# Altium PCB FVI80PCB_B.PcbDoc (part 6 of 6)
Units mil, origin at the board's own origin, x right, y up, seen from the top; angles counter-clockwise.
Board outline 3540 x 3115 mil, 12 copper layers (Top Layer, Int1(GND), Int2(Signal), Int3(GND), Int4(Signal), Int5 (GND&PW), Int6 (GND&PW), Int7(Signal), Int8(GND), Int9(Signal), Int10(GND), Bottom Layer), stack 77.136 mil thick; 488 components, 321 nets, 1809 pads, 882 vias.
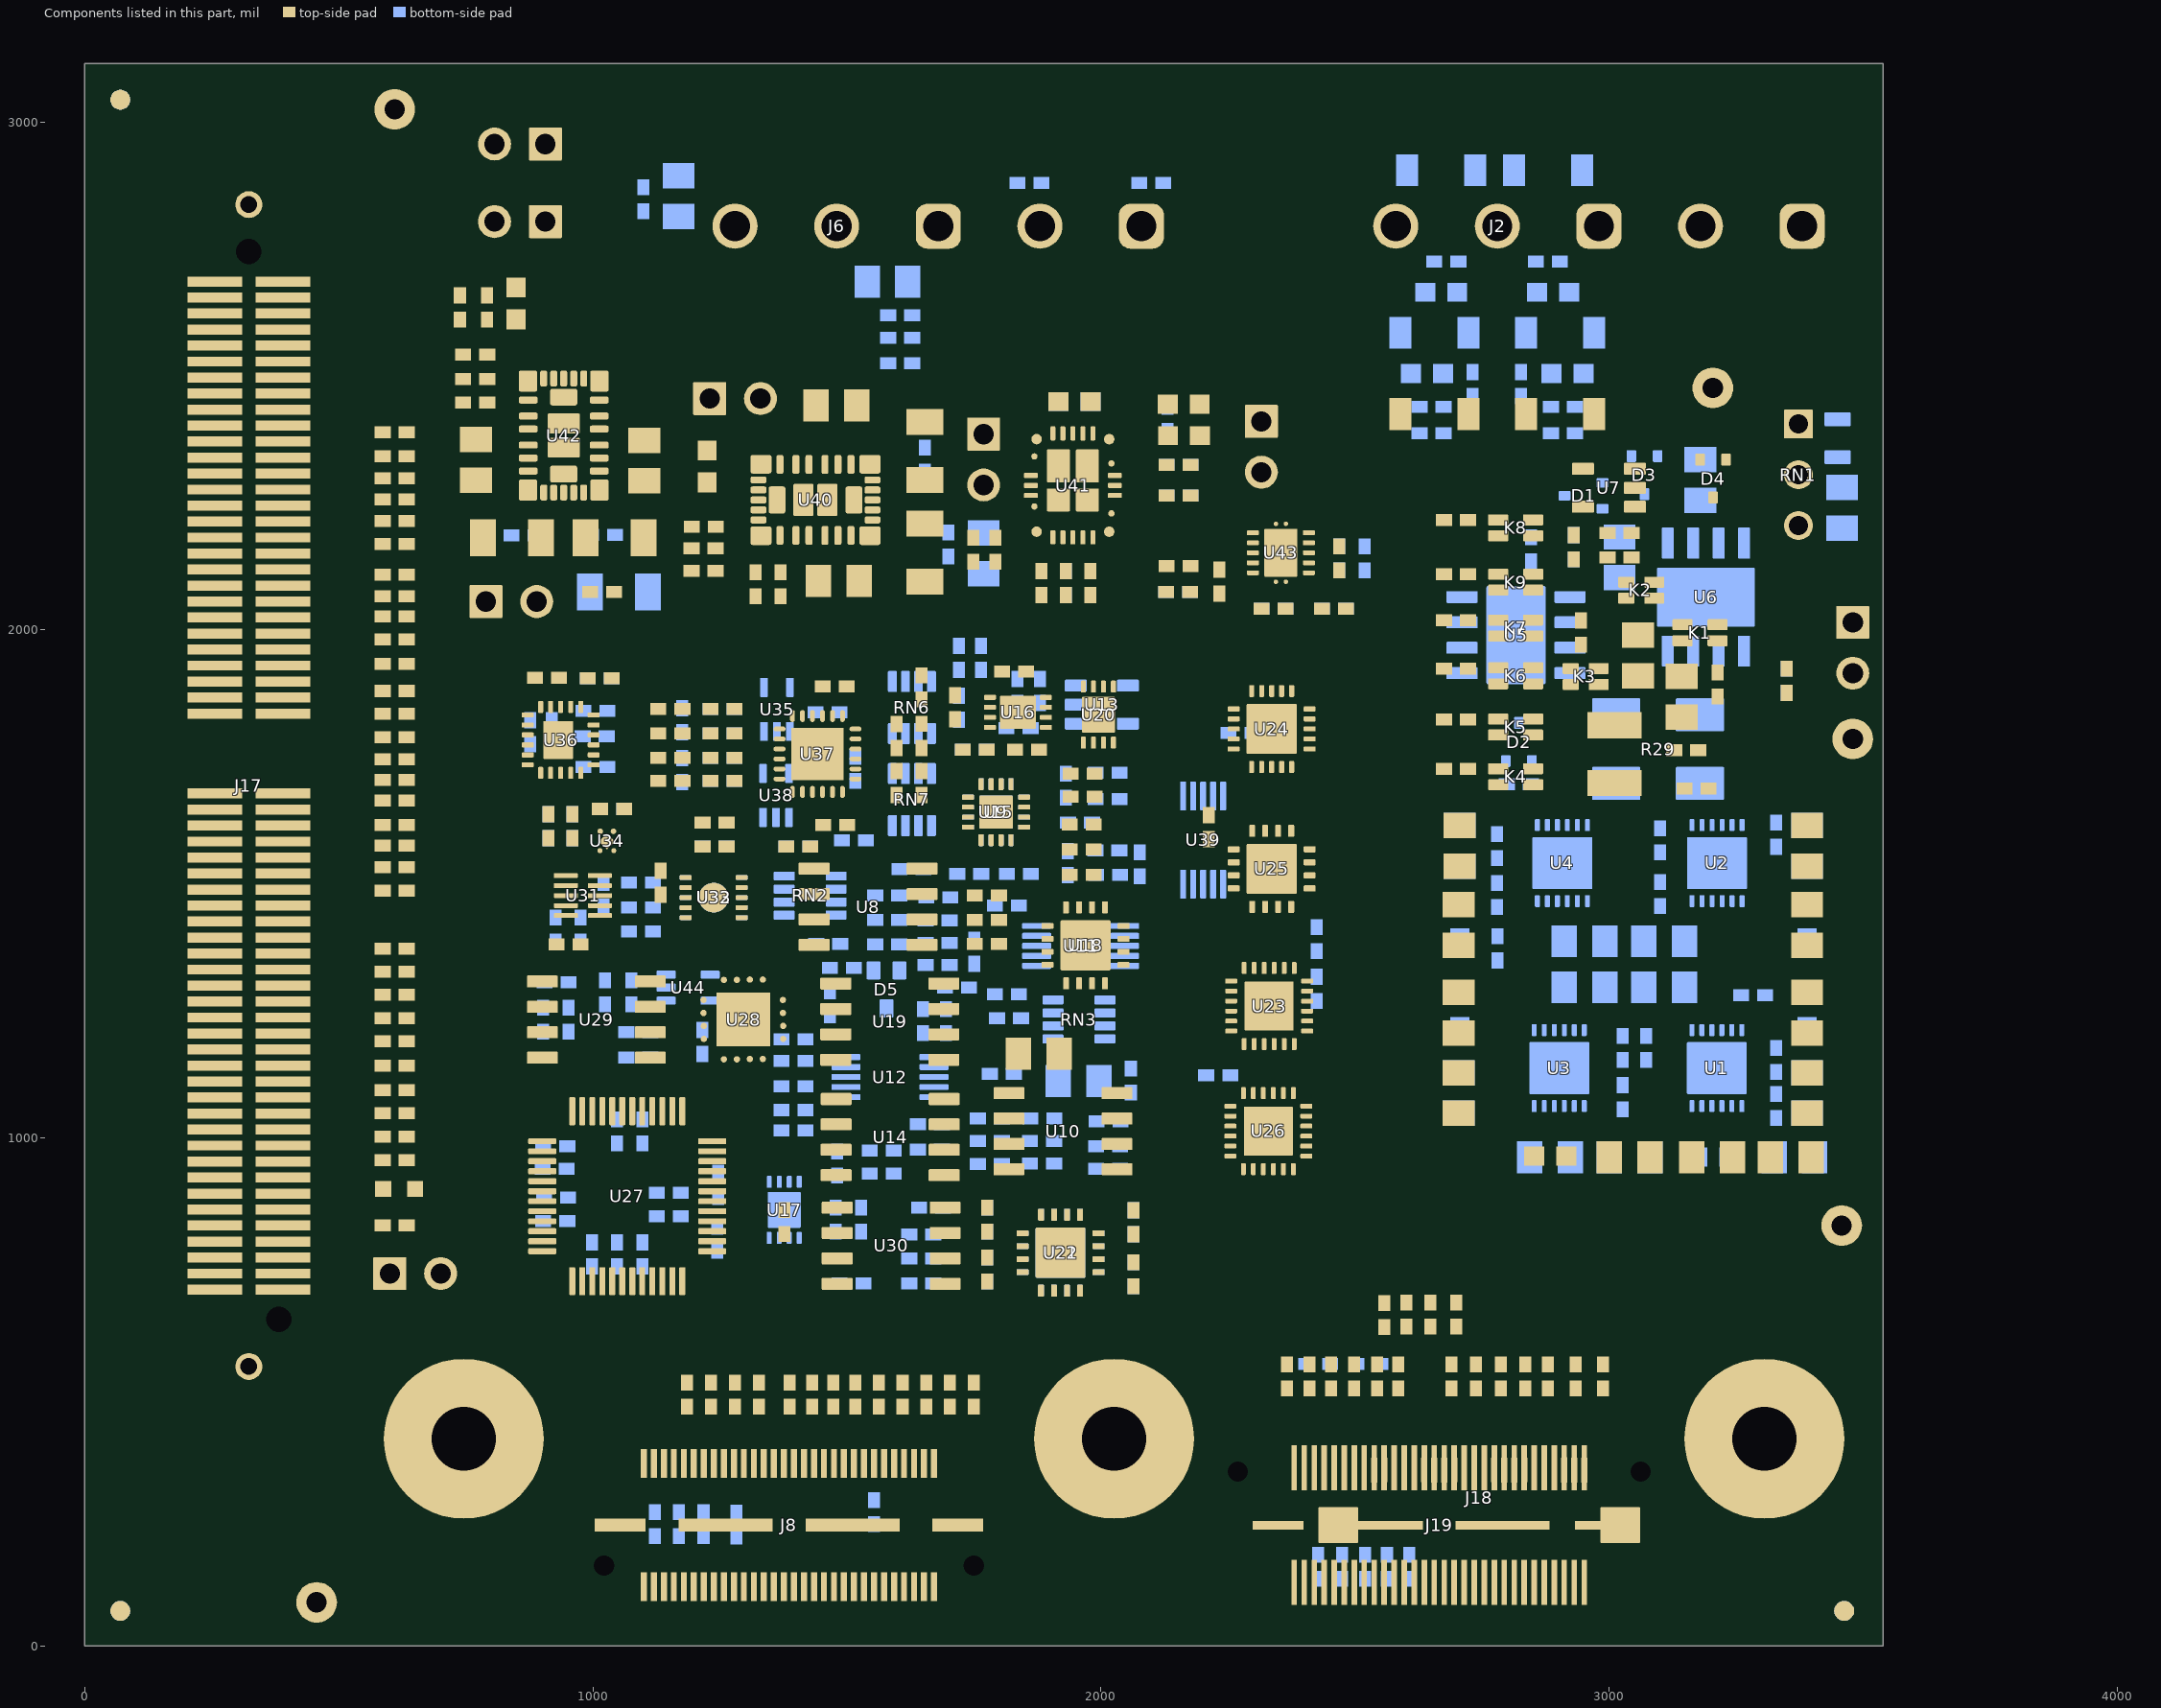
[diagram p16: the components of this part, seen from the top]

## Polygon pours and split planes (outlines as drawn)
NetK4_4 on Bottom Layer "BOTTOM_LAYER_NETK4_4_P132" (solid, pour order 132): 3228,1682 3247,1701 3409,1701 3409,1751 3122,1751 3115,1744 3115,1671 3133,1653 3199,1653
NetK5_4 on Bottom Layer "Bottom Layer-NetK5_4" (solid, pour order 131): 3120,1783 3125,1778 3410,1778 3410,1847 3242,1847 3230,1859 3230,1871 3223,1878 3120,1878
GNDB on Bottom Layer "BOTTOM_LAYER_GNDB_P128" (solid, pour order 128): 3044,1641 3044,1652 3079,1687 3079,1746 3073,1752 2932,1752 2908,1776 2826,1776 2818,1768 2818,1728 2827,1719 2905,1719 2983,1641
NetK3_3 on Bottom Layer "BOTTOM_LAYER_NETK3_3_P126" (solid, pour order 126): 2998,1945 3082,1945 3088,1939 3088,1783 3083,1778 2949,1778 2944,1783 2944,1841 2994,1891 2994,1941
GNDB on Bottom Layer "Int1(GND)-GNDB" (solid, pour order 119): 3541,0 3541,745 3356,745 3356,888.07 2641.5,888.07 2641.5,1826 2641.5,2244.12 2496.69,2244.12 2496.69,2536.69 2494.03,2539.36 2282.07,2539.36 2282.07,3113.23 0,3115.23 0,0
VDD_15VN on Bottom Layer "BOTTOM_LAYER_VDD_15VN_P034" (solid, pour order 34): 871,2841 1336.87,2841 1336.87,2747.83 871,2747.83
GNDA on Bottom Layer "BOTTOM_LAYER_GNDA_P020" (solid, pour order 20): 2658,2451.14 2671.23,2464.37 2888.24,2464.37 2901.47,2451.14 2901.47,2375.79 2658,2375.79
VCC_LV_ext on Bottom Layer "BOTTOM_LAYER_VCC_LV_EXT_P016" (solid, pour order 16): 2930,2489 2930,2464 2917,2451 2917,2376 2976,2376 2994,2394 2994,2483 2969,2508 2950,2489
VEE_LV_ext on Bottom Layer "BOTTOM_LAYER_VEE_LV_EXT_P015" (solid, pour order 15): 2630,2489 2630,2464 2643,2451 2643,2376 2584,2376 2566,2394 2566,2483 2591,2508 2610,2489
NetC142_2 on Bottom Layer "BOTTOM_LAYER_NETC142_2_P014" (solid, pour order 14): 2682,2661.56 2682,2551.88 2653.01,2522.9 2653.01,2490.61 2732.63,2490.61 2746.4,2504.38 2746.4,2621.61 2722.4,2645.61
NetC9_1 on Bottom Layer "BOTTOM_LAYER_NETC9_1_P006" (solid, pour order 6): 2935.7,2646.3 2888,2694 2888,2780.07 2942.93,2835 3025,2835 3025,2729.6 3022,2726.6 2941.7,2646.3
NetC14_2 on Bottom Layer "BOTTOM_LAYER_NETC14_2_P009" (solid, pour order 9): 2551,2837 2606,2837 2672,2771 2672,2690 2658,2676 2625,2676 2618,2683 2543,2758 2543,2808
NetC140_1 on Bottom Layer "BOTTOM_LAYER_NETC140_1_P007" (solid, pour order 7): 2878,2677.85 2878,2554.67 2908.39,2524.29 2908.39,2492 2828.77,2492 2815,2505.77 2815,2623 2864.53,2672.53
GNDB on Bottom Layer "BOTTOM_LAYER_GNDB_P000" (solid, pour order 0): 2967.6,1419 3093,1419 3093,1265 2967.6,1265
GNDB on Int10(GND) "Int8(GND)-GNDB" (solid, pour order 110): 0,0 3541,0 3541,745 3356,745 3356,888.07 2641.5,888.07 2641.5,1617.67 2641.5,1632.5 2695,1686 3043,1686 3059,1702 3059,1714 3043,1730 2988,1730 2944,1774 2694,1774 2642,1826 2641.5,1826 2641.5,2244.12 2496.69,2244.12 2496.69,2536.69 2494.03,2539.36 2282.07,2539.36 2282.07,3113.23 0,3115.23
GNDB on Top Layer "Int1(GND)-GNDB" (solid, pour order 150): 3541,0 3541,745 3356,745 3356,888.07 2641.5,888.07 2641.5,1826 2641.5,2244.12 2496.69,2244.12 2496.69,2536.69 2494.03,2539.36 2282.07,2539.36 2282.07,3113.23 0,3115.23 0,0
VDD_3V3 on Top Layer "TOP_LAYER_VDD_3V3_P108" (solid, pour order 108): 2447,2198 2448,2197 2530,2197 2530,2147 2447,2147
NetK1_3 on Top Layer "TOP_LAYER_NETK1_3_P043" (solid, pour order 43): 3164,2018 3110,2073 3074,2073 3070,2069 3070,2053 3127,2000
NetK1_4 on Top Layer "Top Layer-NetK1_4" (solid, pour order 33): 3125,1921 3174,1921 3174,1934 3165,1943 3165,1982.87 3128,1978 3125,1975
NetK1_3 on Top Layer "TOP_LAYER_NETK1_3_P032" (solid, pour order 32): 2960,1930 2961,1929 3000,1929 3036,1965 3083,1965 3083,1978 3084,1979 3048,2015 3011,2015 2982,1986 2982,1956 2960,1934
NetK3_3 on Top Layer "Top Layer-NetK3_3" (solid, pour order 26): 2958,1831 3051,1831 3050,1832 3072,1832 3072,1853 3029,1853 2999,1883 2999,1893 2961,1888 2958,1885
NetJ1_1 on Top Layer "TOP_LAYER_NETJ1_1_P025" (solid, pour order 25): 3070,2084 3131,2084 3131,2138 3110,2159 3070,2119
NetK1_3 on Top Layer "TOP_LAYER_NETK1_3_P005" (solid, pour order 5): 3068,2053 3112.34,2053 3087.3,1988.89 3022,2012
GNDB on Int7(Signal) "Int1(GND)-GNDB" (solid, pour order 102): 3541,0 3541,745 3356,745 3356,888.07 2641.5,888.07 2641.5,1826 2641.5,2244.12 2496.69,2244.12 2496.69,2536.69 2494.03,2539.36 2282.07,2539.36 2282.07,3113.23 0,3115.23 0,0
GNDB on Int6 (GND&PW) "Int1(GND)-GNDB" (solid, pour order 148): 3541,0 3541,745 3356,745 3356,888.07 2641.5,888.07 2641.5,1826 2641.5,2244.12 2496.69,2244.12 2496.69,2536.69 2494.03,2539.36 2282.07,2539.36 2282.07,3113.23 0,3115.23 0,0
VDD_12VN on Int6 (GND&PW) "INT6_(GND&PW)_VDD_12VN_P138" (solid, pour order 138): 843,2094 845,2096 936,2096 1039,1993 1661,1993 1790,1864 1790,1829 1772,1811 1278,1811 1172,1917 923,1917 843,1997
VDD_12VP on Int6 (GND&PW) "INT6_(GND&PW)_VDD_12VP_P137" (solid, pour order 137): 1686,2225 2339.02,2225 2339.02,1779.96 2323.28,1764.22 1836.79,1764.22 1836.79,1951.16 1871.63,1986 2080,1986 2080,1993.71 2172.57,2086.28 2154.85,2104 1698.02,2104 1686,2116.02
VDD_12VP on Int6 (GND&PW) "INT6_(GND&PW)_VDD_12VP_P136" (solid, pour order 136): 2030.48,1111.14 2041.34,1122 2111.86,1122 2369.7,864.15 2868.77,864.15 3000.72,732.2 3000.72,465.72 2970,435 2915.13,435 2832,518.13 2832,688 2830.92,688 2766.36,752.56 2254.92,752.56 2027.79,979.69
VDD_12VP on Int6 (GND&PW) "Int6 (GND&PW)-VDD_12VP" (solid, pour order 133): 1111,646 1256.18,646 1515.72,905.54 1580.02,841.24 1700.07,841.24 1714.09,855.26 1714.09,873.05 1590,997.14 1244.45,997.14 1244.45,842.96 1094.06,692.58 1094.06,660
VDD_12VP on Int6 (GND&PW) "INT6_(GND&PW)_VDD_12VP_P120" (solid, pour order 120): 1656.2,1551.01 1305.85,1551.01 1129.11,1374.27 1129.11,1179.67 1516.51,1179.67 1614.65,1081.53 1663.6,1081.53 1663.6,1248.63 1709.63,1294.66 1709.63,1316.21 1664.65,1361.19 1664.65,1542.56
VDD_12VP on Int6 (GND&PW) "INT6_(GND&PW)_VDD_12VP_P063" (solid, pour order 63): 1686,2320 1862,2320 1862,2130 1686,2130
VDD_3V3 on Int6 (GND&PW) "Int6 (GND&PW)-VDD_3V3" (solid, pour order 59): 2233.01,1088.36 2500.1,1088.36 2500.1,1567.53 2629.16,1567.53 2629.16,1718.08 2712.16,1718.08 2712.16,1860.21 2641.5,1860.21 2641.5,2243.25 2449.75,2243.25 2448,2245 2447.01,2118.78 2447.01,1743.53 1991.83,1743.53 1991.83,1745.09 1691.83,1745.09 881,1745.09 881,1624.36 881.34,1624.36 881.34,1000 811,1000 811,824 1111,824 1111,1000 1005.56,1000 1005.56,1569.09 1691.83,1569.09 1819.99,1569.09 1819.99,1567.53 2331.28,1567.53 2331.28,1155.98 2233.01,1155.98
VDD_15VP on Int6 (GND&PW) "INT6_(GND&PW)_VDD_15VP_P036" (solid, pour order 36): 1649.51,2635 1599.18,2635 1599.18,2515.35 776.35,2515.35 731,2470 731,2384 763.7,2351.3 1296,2351.3 1296,2116.75 1360.75,2052 1448,2052 1457,2061 1457,2373.58 1536.58,2373.58 1650.46,2487.46
GNDA on Int6 (GND&PW) "Int6 (GND&PW)-GNDA" (solid, pour order 19): 2670.66,923 3433,923 3433,1711 3095.59,1711 3095.59,1632 3298,1632 3298,1048.52 2792.15,1048.52 2792.15,1645.67 2670.66,1645.67
GNDB on Int5 (GND&PW) "Int1(GND)-GNDB" (solid, pour order 149): 3541,0 3541,745 3356,745 3356,888.07 2641.5,888.07 2641.5,1826 2641.5,2244.12 2496.69,2244.12 2496.69,2536.69 2494.03,2539.36 2282.07,2539.36 2282.07,3113.23 0,3115.23 0,0
VDD_12VP on Int5 (GND&PW) "INT5_(GND&PW)_VDD_12VP_P146" (solid, pour order 146): 2041.76,1070.65 2153.29,1070.65 2391.25,1308.61 2391.25,1438.72 2374.97,1455.01 2189.89,1455.01 2041.76,1292.74
GNDA on Int5 (GND&PW) "INT5_(GND&PW)_GNDA_P012" (solid, pour order 12): 2699,2450 2713.37,2464.37 2842.63,2464.37 2852,2455 2852,2375.79 2699,2375.79
GNDA on Int5 (GND&PW) "INT5_(GND&PW)_GNDA_P022" (solid, pour order 22): 2737,1588 2749,1600 2749,1644 2681,1644 2664,1627 2664,1602 2678,1588
VDD_12VN_0 on Int5 (GND&PW) "INT5_(GND&PW)_VDD_12VN_0_P035" (solid, pour order 35): 849,2837.52 849,2733 900,2682 900,2542 1140,2302 1139,2301 1139,2134 913,2134 812,2033 757,2033 757,2449 731,2475 731,2837.52
VDD_12VP_0 on Int5 (GND&PW) "INT5_(GND&PW)_VDD_12VP_0_P037" (solid, pour order 37): 1297.46,2487.46 1362.46,2487.46 1362.46,2450.92 1469.75,2343.64 1679.87,2343.64 1728.2,2391.97 1728.2,2427 1805.2,2427 1816.63,2415.57 1816.63,2335.55 1771.41,2335.55 1699.79,2263.92 1699.79,2238.79 1628.3,2167.3 1497.99,2167.3 1497.99,2262.8 1488.01,2272.77 1462.86,2272.77 1287.24,2448.39
NetC113_1 on Int5 (GND&PW) "INT5_(GND&PW)_NETC113_1_P039" (solid, pour order 39): 2347.62,2376.63 2317.31,2346.33 2153.16,2346.33 2153.16,2303.02 2106,2303.02 2106,2407 2172.57,2407 2215.57,2450 2345.02,2450 2347.62,2447.41
NetC110_1 on Int5 (GND&PW) "Int5 (GND&PW)-NetC110_1" (solid, pour order 41): 2010.84,2413.47 2141.08,2413.47 2153.16,2425.55 2153.16,2462.95 1889.19,2462.95 1888.14,2464 1888.14,2284.59 1937.44,2284.59 1945.01,2292.16 1945.01,2347.63
VDD_5V on Int5 (GND&PW) "INT5_(GND&PW)_VDD_5V_P042" (solid, pour order 42): 2246,2343.64 2248.69,2346.33 2354.31,2346.33 2354.31,2215.59 2234.85,2096.13 2153.16,2096.13 2153.16,2285.99 2212.18,2345 2249,2345
VDD_12VN on Int5 (GND&PW) "INT5_(GND&PW)_VDD_12VN_P060" (solid, pour order 60): 1677,1696.64 1848,1696.64 1848,1601 1677,1601
VDD_12VN on Int5 (GND&PW) "INT5_(GND&PW)_VDD_12VN_P061" (solid, pour order 61): 1244.5,1285.64 1428,1285.64 1428,1178 1244.5,1178
VDD_12VN on Int5 (GND&PW) "INT5_(GND&PW)_VDD_12VN_P062" (solid, pour order 62): 1195,1521.64 1276,1521.64 1276,1426 1195,1426
GNDA on Int5 (GND&PW) "INT5_(GND&PW)_GNDA_P096" (solid, pour order 96): 2783.4,2773.4 2583.75,2573.75 2773.75,2383.75 2973.6,2583.6
VDD_12VP on Int5 (GND&PW) "INT5_(GND&PW)_VDD_12VP_P139" (solid, pour order 139): 1557.79,1116.57 1659.22,1116.57 1684.29,1091.51 1684.29,931.45 1776.42,839.31 1856.27,839.31 2006.64,688.95 2006.64,603.06 1895.88,603.06 1840.53,658.42 1753.26,658.42 1557.79,853.89
VDD_12VN on Int5 (GND&PW) "INT5_(GND&PW)_VDD_12VN_P140" (solid, pour order 140): 1052,646 1154.05,646 1199.94,691.89 1509.02,691.89 1509.02,1115.64 1528.57,1135.19 1701.63,1135.19 1780.76,1056.05 1780.76,888.53 1913.37,888.53 2026.13,775.77 2116.45,866.1 2116.45,994.24 1970.37,1140.32 1935.02,1140.32 1935.02,1473.09 1897.44,1510.66 1817.11,1510.66 1757.2,1450.75 1757.2,1317.65 1709.83,1317.65 1596.19,1204.02 1488.23,1204.02 1488.23,1358.89 933.08,1914.04 933.08,2084.37 882.84,2084.37 849.55,2051.09 849.55,1842.7 1179.2,1513.05 1179.2,1212.4 1325,1066.6 1324.58,1066.18 1324.58,892.29 1261.52,892.29 1051.23,682
VDD_12VN on Int5 (GND&PW) "INT5_(GND&PW)_VDD_12VN_P141" (solid, pour order 141): 1732.81,1858.71 1733.18,1858.35 1871.63,1858.35 1871.63,1915.46 1910.28,1948.24 2070.86,1801 2223.19,1801 2299.72,1724.48 2404.51,1724.48 2404.51,1792.54 2434.64,1822.68 2454.29,1822.68 2566,1710.97 2566,1150.15 2913.35,802.81 2913.35,515.02 2896.32,498 2791,498 2791,783.11 2450,1124.11 2450,1520.53 2394.5,1520.53 2297.83,1617.19 2205.81,1617.19 2134.01,1688.99 1864.44,1688.99 1864.44,1621.62 1843.82,1601 1677,1601 1677,1810.9 1724.81,1858.71
VDD_5V on Int5 (GND&PW) "Int5 (GND&PW)-VDD_5V" (solid, pour order 144): 1931.06,1957.84 2054.09,1834.81 2472.07,1834.81 2475.12,1837.86 2519.14,1793.84 2630.61,1793.84 2630.61,1930.54 2584.78,1976.37 2518.24,1976.37 2363.33,2131.28 2363.33,2243.25 2185.85,2243.25 2154.85,2212.25 2154.85,2007.05 2144.81,1997 2142.81,1999 1088.1,1999 1058.28,1969.18 1058.28,1823.7 1261.47,1620.51 1461.33,1620.51 1699.35,1858.53 1699.53,1858.35 1822.32,1858.35 1822.32,1866.14 1880,1923.83 1880,1957.84
VDD_5V on Int5 (GND&PW) "INT5_(GND&PW)_VDD_5V_P145" (solid, pour order 145): 837.78,1841.24 814.99,1841.24 800.4,1826.65 800.4,1586.32 800.63,1586.32 1070.31,1316.64 1070.31,913.68 1047.21,890.58 1047.21,768.21 961,682 961,647.18 1030.84,647.18 1109.22,725.56 1109.22,842.63 1157.62,891.04 1157.62,1392.67 855.38,1694.91 855.38,1823.64
VDD_12VP on Int5 (GND&PW) "INT5_(GND&PW)_VDD_12VP_P147" (solid, pour order 147): 1669.5,1580.5 1858.97,1580.5 1920.63,1642.17 1961,1642.17 1961,1613 1855.71,1507.71 1640.78,1507.71 1640.78,1508.8 1627.3,1522.29 1627.3,1538.3
GNDB on Int4(Signal) "Int1(GND)-GNDB" (solid, pour order 116): 3541,0 3541,745 3356,745 3356,888.07 2641.5,888.07 2641.5,1826 2641.5,2244.12 2496.69,2244.12 2496.69,2536.69 2494.03,2539.36 2282.07,2539.36 2282.07,3113.23 0,3115.23 0,0
GNDB on Int2(Signal) "Int8(GND)-GNDB" (solid, pour order 123): 0,0 3541,0 3541,745 3356,745 3356,888.07 2641.5,888.07 2641.5,1617.67 2641.5,1632.5 2695,1686 3043,1686 3059,1702 3059,1714 3043,1730 2988,1730 2944,1774 2694,1774 2642,1826 2641.5,1826 2641.5,2244.12 2496.69,2244.12 2496.69,2536.69 2494.03,2539.36 2282.07,2539.36 2282.07,3113.23 0,3115.23
GNDB on Int3(GND) "Int8(GND)-GNDB" (solid, pour order 122): 0,0 3541,0 3541,745 3356,745 3356,888.07 2641.5,888.07 2641.5,1617.67 2641.5,1632.5 2695,1686 3043,1686 3059,1702 3059,1714 3043,1730 2988,1730 2944,1774 2694,1774 2642,1826 2641.5,1826 2641.5,2244.12 2496.69,2244.12 2496.69,2536.69 2494.03,2539.36 2282.07,2539.36 2282.07,3113.23 0,3115.23
GNDB on Int9(Signal) "Int8(GND)-GNDB" (solid, pour order 121): 0,0 3541,0 3541,745 3356,745 3356,888.07 2641.5,888.07 2641.5,1617.67 2641.5,1632.5 2695,1686 3043,1686 3059,1702 3059,1714 3043,1730 2988,1730 2944,1774 2694,1774 2642,1826 2641.5,1826 2641.5,2244.12 2496.69,2244.12 2496.69,2536.69 2494.03,2539.36 2282.07,2539.36 2282.07,3113.23 0,3115.23
GNDB on Int8(GND) "Int8(GND)-GNDB" (solid, pour order 125): 0,0 3541,0 3541,745 3356,745 3356,888.07 2641.5,888.07 2641.5,1617.67 2641.5,1632.5 2695,1686 3043,1686 3059,1702 3059,1714 3043,1730 2988,1730 2944,1774 2694,1774 2642,1826 2641.5,1826 2641.5,2244.12 2496.69,2244.12 2496.69,2536.69 2494.03,2539.36 2282.07,2539.36 2282.07,3113.23 0,3115.23
GNDB on Int1(GND) "Int8(GND)-GNDB" (solid, pour order 124): 0,0 3541,0 3541,745 3356,745 3356,888.07 2641.5,888.07 2641.5,1617.67 2641.5,1632.5 2695,1686 3043,1686 3059,1702 3059,1714 3043,1730 2988,1730 2944,1774 2694,1774 2642,1826 2641.5,1826 2641.5,2244.12 2496.69,2244.12 2496.69,2536.69 2494.03,2539.36 2282.07,2539.36 2282.07,3113.23 0,3115.23

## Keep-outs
Keep-Out Layer:
  text ".Layer_Name" at 327,-703.49 h60

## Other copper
Top Layer:
  rectangle net VEE_LV_ext: 2810.74,1062.77 3283.18,1613.95
  text ".Layer_Name" at 327,-703.49 h60
Int6 (GND&PW):
  rectangle net VEE_LV_ext: 2810.74,1062.77 3283.18,1613.95
Bottom Layer:
  text ".Layer_Name" at 327,-703.49 h60
Multi-Layer:
  pour cut-out: 2227,30 2227,601 1354,601 1309,646 795,646 795,639 1304.4,639 1349.4,594 2212.13,594 2212.13,30
  pour cut-out: 1158,1999 2161.99,1999 2161.99,2010.18 1158,2010.18
  pour cut-out: 1490,2610 1525,2575 1525,2510 1547.5,2510 1547.5,2650 1630,2650 1640,2660 1640,2730 1710,2730 1735,2755 1735,2835 1720,2850 1450,2850 1425,2825 1425,2770 1450,2745 1460.91,2745 1490,2715

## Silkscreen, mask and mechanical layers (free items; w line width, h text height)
Top Overlay:
  lines w5: 698.58,1976.37 2578.58,1976.37 2578.58,2539.36 698.58,2539.36 698.58,1976.37 ; 857,682 2096,682 2096,1932 857,1932 857,682 ; 2180.26,919.84 2458.3,919.84 2458.3,1908.48 2180.26,1908.48 2180.26,919.84 ; 2630.61,912 3459,912 3459,2539.48 2630.61,2539.48 2630.61,912
  text "GNDB" at 555,3087 h30 r180
  text "GNDB" at 830,3085 h36 r180
  text "+LV" at 980,3085 h36 r180
  text "-LV" at 1310,3085 h36 r180
  text "GNDB" at 1530,3085 h36 r180
  text "+LV" at 1750,3085 h36 r180
  text "-HV" at 2632.94,3085 h36 r180
  text "GNDA" at 2852.94,3085 h36 r180
  text "+HV" at 3032.94,3085 h36 r180
  text "GNDA" at 3250,3085 h36 r180
  text "Vout" at 3450,3085 h36 r180
  text "Gang-" at 1970,3073 h36 r180
  text "Gang+" at 2170,3073 h36 r180
  text "Vout" at 3148.98,2393.6 h30
  text "Vout0" at 3514,1581 h30 r90
  text "20*40" at 2659,867 h30
  text "GNDA" at 3499,646 h30 r90
  text "32*32" at 858,636 h30
  text "GNDB" at 520,44 h30
  text ".Layer_Name" at 327,-703.49 h60
Bottom Overlay:
  circle w10: c2331.67,2743 r196.85
  circle w10: c569,2743 r196.85
  circle w10: c250.51,244 r196.85
  circle w10: c2990,244 r196.85
  text ".Layer_Name" at 327,-703.49 h60
Top Paste:
  text ".Layer_Name" at 327,-703.49 h60
Bottom Paste:
  text ".Layer_Name" at 327,-703.49 h60
Top Solder:
  rectangle: 2810.74,1062.77 3283.18,1613.95
  text ".Layer_Name" at 327,-703.49 h60
  text ".Layer_Name" at 327,-703.49 h60
Bottom Solder:
  text ".Layer_Name" at 327,-703.49 h60
Drill Guide:
  text ".Layer_Name" at 327,-703.49 h60
M1 Board Outline:
  lines w10: -2,0 3540,0 3540,3115 -2,3115 -2,0
  text ".Layer_Name" at -4,-136 h60
M2 Board Dimensions:
  text ".Layer_Name" at -6,-234 h60
M3 3D STEP Top:
  text ".Layer_Name" at 327,-703.49 h60
M4 3D STEP Bottom:
  text ".Layer_Name" at 327,-703.49 h60
M5 Assembly Top:
  lines w10: -542,-775.17 6058,-775.17 ; -542,-571.83 6060,-571.83 ; -542,-368.5 -542,-978.5 3463,-978.5 6060,-978.5 6060,-368.5 -541.5,-368.5 -541.5,-978.5 1034,-978.5 ; 1923,-978.5 1923,-368.5 ; 3190,-571.83 3190,-368.5 ; 4030,-571.83 4030,-368.5 ; 4652,-985 4652,-782.17
  text "COMPONENTS MARKED 'DNP' SHOULD NOT BE POPULATED." at 676.37,-315 h60
  text "ASSEMBLY VARIANT:" at -465,-325 h60
  text ".VariantName" at 510,-325 h60
  text "PCB VIEWED FROM TOP SIDE" at -478.5,-500.67 h60
  text "BOARD #:" at 1998,-500.67 h60
  text ".PRJ_Number" at 2543.5,-500.67 h60
  text "REV:" at 3388,-500.67 h60
  text ".PCB_Rev" at 3679.5,-500.67 h60
  text "SVN REV:" at 4226,-500.67 h60
  text ".VersionControl_RevNumber" at 4732,-500.67 h60
  text "TID #:" at 1998,-704 h60
  text ".TID" at 2543.5,-704 h60
  text "PLOT NAME =" at -478.5,-909.33 h60
  text ".plot_File_Name" at 327,-909.33 h60
  text "GENERATED    :" at 2000,-909.33 h60
  text ".Print_Date" at 2869.5,-909.33 h60
  text ".Print_Time" at 3598.5,-909.33 h60
  text "TEXAS INSTRUMENTS" at 4863,-909.33 h60
M6 Assembly Bottom:
  lines w10: -542.5,-572.33 6059.5,-572.33 ; -540.5,-775.67 6059.5,-775.67 ; 865.5,-985.5 865.5,-782.67 ; 1487.5,-572.33 1487.5,-369 ; 2327.5,-572.33 2327.5,-369 ; 3594.5,-979 3594.5,-369 ; 4483.5,-979 6059,-979 6059,-369 -542.5,-369 -542.5,-979 2054.5,-979 6059.5,-979 6059.5,-369
  text "COMPONENTS MARKED 'DNP' SHOULD NOT BE POPULATED." at 3415,-305 h60
  text ".VariantName" at 3623,-309 h60
  text "ASSEMBLY VARIANT:" at 4662,-309 h60
  text ".VersionControl_RevNumber" at 785.5,-501.17 h60
  text "SVN REV:" at 1291.5,-501.17 h60
  text ".PCB_Rev" at 1838,-501.17 h60
  text "REV:" at 2129.5,-501.17 h60
  text ".PRJ_Number" at 2974,-501.17 h60
  text "BOARD #:" at 3519.5,-501.17 h60
  text "PCB VIEWED FROM BOTTOM SIDE" at 5996,-501.17 h60
  text ".TID" at 2974,-704.5 h60
  text "TID #:" at 3519.5,-704.5 h60
  text "TEXAS INSTRUMENTS" at 654.5,-909.83 h60
  text ".Print_Time" at 1919,-909.83 h60
  text ".Print_Date" at 2648,-909.83 h60
  text "GENERATED    :" at 3517.5,-909.83 h60
  text ".plot_File_Name" at 5190.5,-909.83 h60
  text "PLOT NAME =" at 5996,-909.83 h60
M9 Title Sheet:
  drawing of 57 lines, arcs and shapes, not listed
  text "1" at 489.84,8191.5 h70
  text "2" at 2985.5,8191.5 h70
  text "3" at 5474.84,8191.5 h70
  text "4" at 7981.51,8191.5 h70
  text "5" at 10480.5,8191.5 h70
  text "6" at 12985.5,8191.5 h70
  text "A" at -666.5,7048.5 h70
  text "A" at 14133.5,7048.5 h70
  text "B" at -666.5,4668.5 h70
  text "B" at 14133.5,4668.5 h70
  text "C" at -666.5,2293.5 h70
  text "C" at 14133.5,2293.5 h70
  text "PROJECT TITLE:" at 11093.5,432.5 h45
  text ".PRJ_Title" at 11143.5,299.17 h70
  text "DESIGNED FOR:" at 11093.5,131.5 h45
  text ".PRJ_Customer" at 11143.5,-8.5 h70
  text "D" at -666.5,-76.5 h70
  text "D" at 14133.5,-76.5 h70
  text "FILE NAME:" at 11093.5,-168.5 h45
  text ".PCB_File_Name_No_Path" at 11143.5,-288.5 h70
  text "Texas Instruments (TI) and/or its licensors do not warrant the accuracy or completeness of this specification" at 6124,-450.34 h45
  text "ENGINEER:" at 11093.5,-458.5 h45
  text "LAYOUT BY:" at 12598.5,-458.5 h45
  text "or any information contained therein. TI and/or its licensors do not warrant that this design will meet" at 6079.01,-563 h45
  text ".PRJ_Engineer" at 11143.5,-613.49 h70
  text ".PCB_Layout" at 12649,-613.49 h70
  text "the specifications, will be suitable for your application or fit for any particular purpose, or will operate in" at 6079.01,-675.67 h45
  text ".Layer_Name" at 327,-703.49 h60
  text "ALTIUM DESIGNER VERSION:" at 12598.5,-768.5 h45
  text "an implementation. TI and/or its licensors do not warrant that the design is production worthy. You should" at 6079.01,-788.33 h45
  text "completely validate and test your design implementation to confirm the system functionality for your application." at 6124,-901 h45
  text ".print_Scale" at 11143.5,-901.83 h70
  text ".Application_BuildNumber" at 12649,-901.83 h70
  text "1" at 489.84,-1108.5 h70
  text "2" at 2985.5,-1108.5 h70
  text "3" at 5474.84,-1108.5 h70
  text "4" at 7981.51,-1108.5 h70
  text "5" at 10480.5,-1108.5 h70
  text "6" at 12985.5,-1108.5 h70
M10 Fab Notes:
  drawing of 189 lines, arcs and shapes, not listed
  text "X" at 952.75,10677.35 h60
  text "DESIGN INFORMATION" at 12132.02,6511.18 h60
  text "MIN. TRACK WIDTH:" at 11487.46,6379.05 h60
  text "6" at 12583.7,6379.05 h60
  text "MIL" at 12738.46,6379.05 h60
  text "7.874" at 12417.32,6257.36 h60
  text "MIN. CLEARANCE:" at 11487.46,6254.92 h60
  text "MIL" at 12738.46,6254.92 h60
  text "MIN. VIA PAD SIZE:" at 11487.46,6130.8 h60
  text "20" at 12553.71,6130.8 h60
  text "MIL" at 12738.46,6130.8 h60
  text "X" at 515.45,6079.24 h60
  text "X" at 3217.45,6059.31 h60
  text "0.15mm (5.9MIL)" at 12182.46,6000.9 h60
  text "MINIMUM ANNULAR RING" at 11158.23,5992.68 h60
  text "EXTERNAL" at 12890.46,5992.68 h60
  text "PER" at 11358.23,5882.55 h60
  text "IPC-D-275 CLASS 2 LEVEL C" at 11578.23,5882.55 h60
  text "MIL, HOLES" at 13066.46,5782.07 h60
  text "+/-" at 12674,5773.48 h60
  text "+/-" at 13528,5773.48 h60
  text "REGISTRATION TOLERANCES:" at 11158.23,5772.42 h60
  text "METAL" at 12358,5772.42 h60
  text "5" at 12934.2,5772.42 h60
  text "3" at 13767.2,5772.42 h60
  text "MIL" at 13883.46,5772.42 h60
  text "HOLE SIZE TOLERANCE (UNLESS OTHERWISE SPECIFIED):" at 11158.23,5674.1 h60
  text "+/-" at 13528,5671.23 h60
  text "3" at 13767.2,5670.17 h60
  text "MIL" at 13883.46,5670.17 h60
  text "MATERIAL:" at 11083.46,5532.52 h60
  text "FR-4 High Tg" at 12069.9,5404 h60
  text "X" at 11924.46,5395.55 h60
  text "FR-408" at 11504.46,5391.49 h60
  text "OTHER" at 12992.46,5391.49 h60
  text "62 MIL (1.6mm) +/-10%" at 11824.56,5248.46 h60
  text "THICKNESS:" at 11158.23,5240.24 h60
  text "X" at 12992.46,5240.24 h60
  text "OTHER" at 13109.46,5240.24 h60
  text "2mm" at 13507.46,5231.24 h60
  text "TOLERANCE:" at 11158.23,5101.92 h60
  text "ANSI IPC-6012 TYPE 3 CLASS 2" at 12184.48,5101.92 h60
  text "OTHER +/-" at 12184.46,4957.73 h60
  text "BOW & TWIST:" at 11158.23,4812.55 h60
  text "X" at 12006.46,4812.55 h60
  text "ANSI IPC-6012 TYPE 3 CLASS 2" at 12184.48,4812.55 h60
  text "OTHER +/-" at 12184.46,4665.85 h60
  text "DRILLING:" at 11083.46,4535.23 h60
  text "X" at 11818.46,4429.55 h60
  text "NC_DRILL FILES" at 12844.46,4430.04 h60
  text "REFERENCE:" at 11158.23,4426.1 h60
  text "AS SHOWN" at 11993.46,4426.1 h60
  text "OTHER" at 13142.46,4283.85 h60
  text "X" at 12296.46,4282.55 h60
  text "PTH COPPER THICKNESS:" at 11157.91,4280.32 h60
  text "20-30 um" at 12425.14,4280.32 h60
  text "BOARD FINISH:" at 11083.46,4132.73 h60
  text "X" at 12703.46,4025.55 h60
  text "SILKSCREEN:" at 11238.68,4022.6 h60
  text "TOP" at 12313.46,4022.6 h60
  text "BOTTOM" at 12824.46,4022.6 h60
  text "X" at 12193.46,4016.55 h60
  text "SILKSCREEN COLOR:" at 11238.68,3867.41 h60
  text "X" at 12190.46,3866.55 h60
  text "WHITE" at 12313.46,3867.41 h60
  text "OTHER" at 12824.46,3867.41 h60
  text "X" at 12325.46,3728.55 h60
  text "GREEN" at 12444.46,3723.96 h60
  text "OTHER" at 13062.46,3723.96 h60
  text "SOLDER RESIST COLOR:" at 11238.68,3717.1 h60
  text "MATTE" at 12444.46,3569.71 h60
  text "SEMI-GLOSS" at 13062,3569.07 h60
  text "IMMERSION GOLD (ENIG)" at 12144.46,3396.94 h60
  text "X" at 11956.46,3390.55 h60
  text "ENEPIG" at 13482,3389.72 h60
  text "SURFACE FINISH:" at 11083.46,3388.72 h60
  text "IMM. TIN/SILVER OR EQUIV" at 11413,3251.4 h60
  text "OTHER" at 12844.46,3247.47 h60
  text "ARRAY/PANEL:" at 11083.46,3092.09 h60
  text "CUT AND TRIM PER M1 BOARD OUTLINE" at 12144.46,3083.87 h60
  text "N.C. ROUTE" at 12144.46,2947.9 h60
  text "V. SCORE" at 13010.46,2947.9 h60
  text "CERTIFICATION:" at 11083.46,2818.77 h60
  text "MATERIALS AND WORKMANSHIP FOR ALL PCBS" at 11808.46,2818.77 h60
  text "TO MEET OR EXCEED THE REQUIREMENTS OF:" at 11808.46,2724.71 h60
  text "ANSI IPC-A-600F CLASS ->" at 11573.96,2596.08 h60
  text "2" at 13331.96,2596.08 h60
  text "1" at 13016.96,2594.58 h60
  text "3" at 13685.96,2594.58 h60
  text "X" at 13213.46,2593.55 h60
  text "X" at 11433.46,2587.55 h60
  text "RoHS" at 12385.96,2448.4 h60
  text "OTHER" at 13030.36,2448.4 h60
  text "PER ORDER" at 13427.42,2448.4 h60
  text "ALL BOARDS MUST MEET OR EXCEED UL94-V0 REQUIREMENTS." at 11111,2294.57 h60
  text "PCB MUST BEAR THE UL94V-0 UL REGISTERED MATERIAL ID NUMBER" at 11111,2178.5 h60
  text "ADDITIONAL REQUIREMENTS:" at 11083.46,2009.08 h60
  text "MICROSECTION:" at 11158.23,1901.95 h60
  text "YES" at 12063.96,1901.95 h60
  text "REQUIRED" at 12925.46,1757.62 h60
  text "X" at 12806.46,1755.55 h60
  text "BARE BOARD ELEC. TEST:" at 11158.23,1754.77 h60
  text "NONE" at 12463.96,1754.77 h60
  text "PER ORDER" at 13517.46,1754.77 h60
  text "XX MIL VIAS REQUIRE NON-CONDUCTIVE FILL AND PLANARIZE" at 11326.38,1549.82 h59
  text "7.87mil MIL VIAS REQUIRE CONDUCTIVE FILL AND PLANARIZE" at 11334.38,1445.84 h60
  text "X" at 11215,1440 h60
  text "OUTER XX MIL TRACES REQUIRE 50 OHM SINGLE-ENDED IMPEDANCE" at 11333.39,1282.46 h58
  text "LAYER 2 & 3 (INNER LAYERS) XX MIL WIDE, XX MIL SPACE / TRACES REQUIRE 100 OHM DIFFERENTIAL IMPEDANCE" at 11325.39,1046.75 h60
  text ".Layer_Name" at 327,-703.49 h60
M11 Gerber Information:
  lines w10: -542,-775.17 6058,-775.17 ; -542,-571.83 6060,-571.83 ; -542,-368.5 -542,-978.5 3463,-978.5 6060,-978.5 6060,-368.5 -541.5,-368.5 -541.5,-978.5 1034,-978.5 ; 1923,-978.5 1923,-368.5 ; 3190,-571.83 3190,-368.5 ; 4030,-571.83 4030,-368.5 ; 4652,-985 4652,-782.17
  text "ALL ARTWORK VIEWED FROM TOP SIDE" at -478.5,-500.67 h60
  text "BOARD #:" at 1998,-500.67 h60
  text ".PRJ_Number" at 2543.5,-500.67 h60
  text "REV:" at 3388,-500.67 h60
  text ".PCB_Rev" at 3679.5,-500.67 h60
  text "SVN REV:" at 4226,-500.67 h60
  text ".VersionControl_RevNumber" at 4732,-500.67 h60
  text "LAYER NAME =" at -478.5,-703.49 h60
  text "TID #:" at 1998,-704 h60
  text ".TID" at 2543.5,-704 h60
  text "PLOT NAME =" at -478.5,-909.33 h60
  text ".plot_File_Name" at 327,-909.33 h60
  text "GENERATED    :" at 2000,-909.33 h60
  text ".Print_Date" at 2869.5,-909.33 h60
  text ".Print_Time" at 3598.5,-909.33 h60
  text "TEXAS INSTRUMENTS" at 4863,-909.33 h60
M12 Stackup:
  drawing of 153 lines, arcs and shapes, not listed
  text "Layer" at 6910.47,7390 h60
  text "Name" at 7320.39,7390 h60
  text "Material" at 8650,7390 h60
  text "Thickness" at 9249.85,7390 h60
  text "Constant" at 9899.69,7390 h60
  text "Top Overlay" at 7320.39,7270 h60
  text "Top Solder" at 7320.39,7150 h60
  text "SM-001" at 8650,7150 h60
  text "1.00mil" at 9249.85,7150 h60
  text "4" at 9899.69,7150 h60
  text "Top Surface Finish" at 7320.39,7030 h60
  text "PbSn" at 8650,7030 h60
  text "0.79mil" at 9249.85,7030 h60
  text "1" at 6910.47,6910 h60
  text "Top Layer" at 7320.39,6910 h60
  text "CF-004" at 8650,6910 h60
  text "1.38mil" at 9249.85,6910 h60
  text "Dielectric 2" at 7320.39,6790 h60
  text "PP-017" at 8650,6790 h60
  text "5.10mil" at 9249.85,6790 h60
  text "4.3" at 9899.69,6790 h60
  text "2" at 6910.47,6670 h60
  text "Int1(GND)" at 7320.39,6670 h60
  text "CF-004" at 8650,6670 h60
  text "1.38mil" at 9249.85,6670 h60
  text "Dielectric 8" at 7320.39,6550 h60
  text "PP-006" at 8650,6550 h60
  text "2.80mil" at 9249.85,6550 h60
  text "4.1" at 9899.69,6550 h60
  text "3" at 6910.47,6430 h60
  text "Int2(Signal)" at 7320.39,6430 h60
  text "CF-004" at 8650,6430 h60
  text "1.38mil" at 9249.85,6430 h60
  text "Dielectric 6" at 7320.39,6310 h60
  text "PP-006" at 8650,6310 h60
  text "2.80mil" at 9249.85,6310 h60
  text "4.1" at 9899.69,6310 h60
  text "4" at 6910.47,6190 h60
  text "Int3(GND)" at 7320.39,6190 h60
  text "CF-004" at 8650,6190 h60
  text "1.38mil" at 9249.85,6190 h60
  text "Dielectric 1" at 7320.39,6070 h60
  text "PP-006" at 8650,6070 h60
  text "2.80mil" at 9249.85,6070 h60
  text "4.1" at 9899.69,6070 h60
  text "5" at 6910.47,5950 h60
  text "Int4(Signal)" at 7320.39,5950 h60
  text "CF-004" at 8650,5950 h60
  text "1.38mil" at 9249.85,5950 h60
  text "Dielectric 10" at 7320.39,5830 h60
  text "PP-006" at 8650,5830 h60
  text "2.80mil" at 9249.85,5830 h60
  text "4.1" at 9899.69,5830 h60
  text "6" at 6910.47,5710 h60
  text "Int5 (GND&PW)" at 7320.39,5710 h60
  text "CF-004" at 8650,5710 h60
  text "1.38mil" at 9249.85,5710 h60
  text "Dielectric 3" at 7320.39,5590 h60
  text "Core-039" at 8650,5590 h60
  text "28.00mil" at 9249.85,5590 h60
  text "4.8" at 9899.69,5590 h60
  text "7" at 6910.47,5470 h60
  text "Int6 (GND&PW)" at 7320.39,5470 h60
  text "CF-004" at 8650,5470 h60
  text "1.38mil" at 9249.85,5470 h60
  text "Dielectric 11" at 7320.39,5350 h60
  text "PP-006" at 8650,5350 h60
  text "2.80mil" at 9249.85,5350 h60
  text "4.1" at 9899.69,5350 h60
  text "8" at 6910.47,5230 h60
  text "Int7(Signal)" at 7320.39,5230 h60
  text "CF-004" at 8650,5230 h60
  text "1.38mil" at 9249.85,5230 h60
  text "Dielectric 5" at 7320.39,5110 h60
  text "PP-006" at 8650,5110 h60
  text "2.80mil" at 9249.85,5110 h60
  text "4.1" at 9899.69,5110 h60
  text "9" at 6910.47,4990 h60
  text "Int8(GND)" at 7320.39,4990 h60
  text "CF-004" at 8650,4990 h60
  text "1.38mil" at 9249.85,4990 h60
  text "Dielectric 7" at 7320.39,4870 h60
  text "PP-006" at 8650,4870 h60
  text "2.80mil" at 9249.85,4870 h60
  text "4.1" at 9899.69,4870 h60
  text "10" at 6910.47,4750 h60
  text "Int9(Signal)" at 7320.39,4750 h60
  text "CF-004" at 8650,4750 h60
  text "1.38mil" at 9249.85,4750 h60
  text "Dielectric 9" at 7320.39,4630 h60
  text "PP-006" at 8650,4630 h60
  text "2.80mil" at 9249.85,4630 h60
  text "4.1" at 9899.69,4630 h60
  text "11" at 6910.47,4510 h60
  text "Int10(GND)" at 7320.39,4510 h60
  text "CF-004" at 8650,4510 h60
  text "1.38mil" at 9249.85,4510 h60
  text "Dielectric 4" at 7320.39,4390 h60
  text "PP-017" at 8650,4390 h60
  text "5.10mil" at 9249.85,4390 h60
  text "4.3" at 9899.69,4390 h60
  text "12" at 6910.47,4270 h60
  text "Bottom Layer" at 7320.39,4270 h60
  text "CF-004" at 8650,4270 h60
  text "1.38mil" at 9249.85,4270 h60
  text "Bottom Surface Finish" at 7320.39,4150 h60
  text "PbSn" at 8650,4150 h60
  text "0.79mil" at 9249.85,4150 h60
  text "Bottom Solder" at 7320.39,4030 h60
  text "SM-001" at 8650,4030 h60
  text "1.00mil" at 9249.85,4030 h60
  text "4" at 9899.69,4030 h60
  text "Bottom Overlay" at 7320.39,3910 h60
  text ".Layer_Name" at 327,-703.49 h60
M13 Component Bodies Top:
  text ".Layer_Name" at 327,-703.49 h60
M14 Component Bodies Bottom:
  text ".Layer_Name" at 327,-703.49 h60
M15 Courtyards Top:
  text ".Layer_Name" at 327,-703.49 h60
M16 Courtyards Bottom:
  text ".Layer_Name" at 327,-703.49 h60
Drill Drawing:
  circle w10: c-306.48,7210.33 r20
  circle w10: c-306.48,7210.33 r33.33
  circle w10: c-306.48,7060.33 r33.33
  lines w10: -339.81,5977 -273.15,5977 -273.15,6043.67 -339.81,6043.67 -339.81,5977 ; -339.81,6127 -273.15,6127 -273.15,6193.67 -339.81,6193.67 -339.81,6127 ; -339.81,6277 -306.48,6293.67 -273.15,6277 -289.81,6310.33 -273.15,6343.67 -306.48,6327 -339.81,6343.67 -323.15,6310.33 -339.81,6277 ; -339.81,6443.67 -323.15,6443.67 -306.48,6427 -289.81,6443.67 -273.15,6443.67 -289.81,6460.33 -273.15,6477 -289.81,6477 -306.48,6493.67 -323.15,6477 -339.81,6477 -323.15,6460.33 -339.81,6443.67 ; -339.81,6643.67 -273.15,6643.67 -306.48,6577 -339.81,6643.67 ; -339.81,6743.67 -323.15,6743.67 -323.15,6727 -289.81,6727 -289.81,6743.67 -273.15,6743.67 -273.15,6777 -289.81,6777 -289.81,6793.67 -323.15,6793.67 -323.15,6777 -339.81,6777 -339.81,6743.67 ; -339.81,6910.33 -306.48,6877 -273.15,6910.33 -306.48,6943.67 -339.81,6910.33 ; -339.81,7327 -339.81,7343.67 -323.15,7360.33 -339.81,7377 -339.81,7393.67 -323.15,7393.67 -306.48,7377 -289.81,7393.67 -273.15,7393.67 -273.15,7377 -289.81,7360.33 -273.15,7343.67 -273.15,7327 -289.81,7327 -306.48,7343.67 -323.15,7327 -339.81,7327 ; -326.48,5990.33 -286.48,5990.33 -286.48,6030.33 -326.48,6030.33 -326.48,5990.33
  lines w15: -399.61,5932 6820.43,5932 ; -399.61,7432 6820.43,7432 ; 151.27,5782 151.27,7582 ; 741.11,5782 741.11,7582 ; 1890.78,5782 1890.78,7582 ; 2396.65,5782 2396.65,7582 ; 3130.46,5782 3130.46,7582 ; 4630.01,5782 4630.01,7582 ; 5219.85,5782 5219.85,7582 ; 5965.65,5782 5965.65,7582 ; -399.61,5782 6820.43,5782 6820.43,7582 -399.61,7582 -399.61,5782
  text "Symbol" at -309.61,7477 h72
  text "Count" at 196.27,7477 h72
  text "Hole Size" at 786.11,7477 h72
  text "Plated" at 1935.78,7477 h72
  text "Hole Type" at 2441.65,7477 h72
  text "Drill Layer Pair" at 3175.46,7477 h72
  text "Via/Pad" at 4675.01,7477 h72
  text "Pad Shape" at 5264.85,7477 h72
  text "Template" at 6010.65,7477 h72
  text "2" at 196.27,7327 h60
  text "33.07mil (0.840mm)" at 786.11,7327 h60
  text "PTH" at 1935.78,7327 h60
  text "Round" at 2441.65,7327 h60
  text "Top Layer - Bottom Layer" at 3175.46,7327 h60
  text "Pad" at 4675.01,7327 h60
  text "Rounded" at 5264.85,7327 h60
  text "c135h84" at 6010.65,7327 h60
  text "2" at 196.27,7177 h60
  text "40.00mil (1.016mm)" at 786.11,7177 h60
  text "NPTH" at 1935.78,7177 h60
  text "Round" at 2441.65,7177 h60
  text "Top Layer - Bottom Layer" at 3175.46,7177 h60
  text "Pad" at 4675.01,7177 h60
  text "Rounded" at 5264.85,7177 h60
  text "c-102hn102" at 6010.65,7177 h60
  text "2" at 196.27,7027 h60
  text "40.16mil (1.020mm)" at 786.11,7027 h60
  text "NPTH" at 1935.78,7027 h60
  text "Round" at 2441.65,7027 h60
  text "Top Layer - Bottom Layer" at 3175.46,7027 h60
  text "Pad" at 4675.01,7027 h60
  text "Rounded" at 5264.85,7027 h60
  text "c0hn102" at 6010.65,7027 h60
  text "2" at 196.27,6877 h60
  text "50.00mil (1.270mm)" at 786.11,6877 h60
  text "NPTH" at 1935.78,6877 h60
  text "Round" at 2441.65,6877 h60
  text "Top Layer - Bottom Layer" at 3175.46,6877 h60
  text "Pad" at 4675.01,6877 h60
  text "Rounded" at 5264.85,6877 h60
  text "c3hn127m90" at 6010.65,6877 h60
  text "3" at 196.27,6727 h60
  text "37.40mil (0.950mm)" at 786.11,6727 h60
  text "PTH" at 1935.78,6727 h60
  text "Round" at 2441.65,6727 h60
  text "Top Layer - Bottom Layer" at 3175.46,6727 h60
  text "Pad" at 4675.01,6727 h60
  text "(Mixed)" at 5264.85,6727 h60
  text "(Mixed)" at 6010.65,6727 h60
  text "3" at 196.27,6577 h60
  text "125.98mil (3.200mm)" at 786.11,6577 h60
  text "PTH" at 1935.78,6577 h60
  text "Round" at 2441.65,6577 h60
  text "Top Layer - Bottom Layer" at 3175.46,6577 h60
  text "Pad" at 4675.01,6577 h60
  text "Rounded" at 5264.85,6577 h60
  text "c800h320z356" at 6010.65,6577 h60
  text "5" at 196.27,6427 h60
  text "11.81mil (0.300mm)" at 786.11,6427 h60
  text "PTH" at 1935.78,6427 h60
  text "Round" at 2441.65,6427 h60
  text "Top Layer - Bottom Layer" at 3175.46,6427 h60
  text "Via" at 4675.01,6427 h60
  text "Rounded" at 5264.85,6427 h60
  text "v60h30m0mx0" at 6010.65,6427 h60
  text "10" at 196.27,6277 h60
  text "59.06mil (1.500mm)" at 786.11,6277 h60
  text "PTH" at 1935.78,6277 h60
  text "Round" at 2441.65,6277 h60
  text "Top Layer - Bottom Layer" at 3175.46,6277 h60
  text "Pad" at 4675.01,6277 h60
  text "(Mixed)" at 5264.85,6277 h60
  text "(Mixed)" at 6010.65,6277 h60
  text "21" at 196.27,6127 h60
  text "40.00mil (1.016mm)" at 786.11,6127 h60
  text "PTH" at 1935.78,6127 h60
  text "Round" at 2441.65,6127 h60
  text "Top Layer - Bottom Layer" at 3175.46,6127 h60
  text "Pad" at 4675.01,6127 h60
  text "(Mixed)" at 5264.85,6127 h60
  text "(Mixed)" at 6010.65,6127 h60
  text "863" at 196.27,5977 h60
  text "7.87mil (0.200mm)" at 786.11,5977 h60
  text "PTH" at 1935.78,5977 h60
  text "Round" at 2441.65,5977 h60
  text "Top Layer - Bottom Layer" at 3175.46,5977 h60
  text "Via" at 4675.01,5977 h60
  text "Rounded" at 5264.85,5977 h60
  text "(Mixed)" at 6010.65,5977 h60
  text "913 Total" at 196.27,5827 h60
  text ".Layer_Name" at 327,-703.49 h60
M17 Embedded Cavity:
  text ".Layer_Name" at 327,-703.49 h60
M18 Embedded Assembly:
  text ".Layer_Name" at 327,-703.49 h60
M19 Embedded Keepout:
  text ".Layer_Name" at 327,-703.49 h60

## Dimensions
0,0 to 0,3115.23 on M2 Board Dimensions
3541,0 to 0,0 on M2 Board Dimensions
